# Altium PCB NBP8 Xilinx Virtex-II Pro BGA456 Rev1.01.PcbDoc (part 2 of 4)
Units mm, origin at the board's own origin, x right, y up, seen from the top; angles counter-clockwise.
Board outline 69 x 99.5 mm, 8 copper layers (Top Layer, InternalPlane1, InternalPlane2, MidLayer1, MidLayer2, MidLayer3, MidLayer4, Bottom Layer), stack 1.545 mm thick; 164 components, 314 nets, 1132 pads, 807 vias.
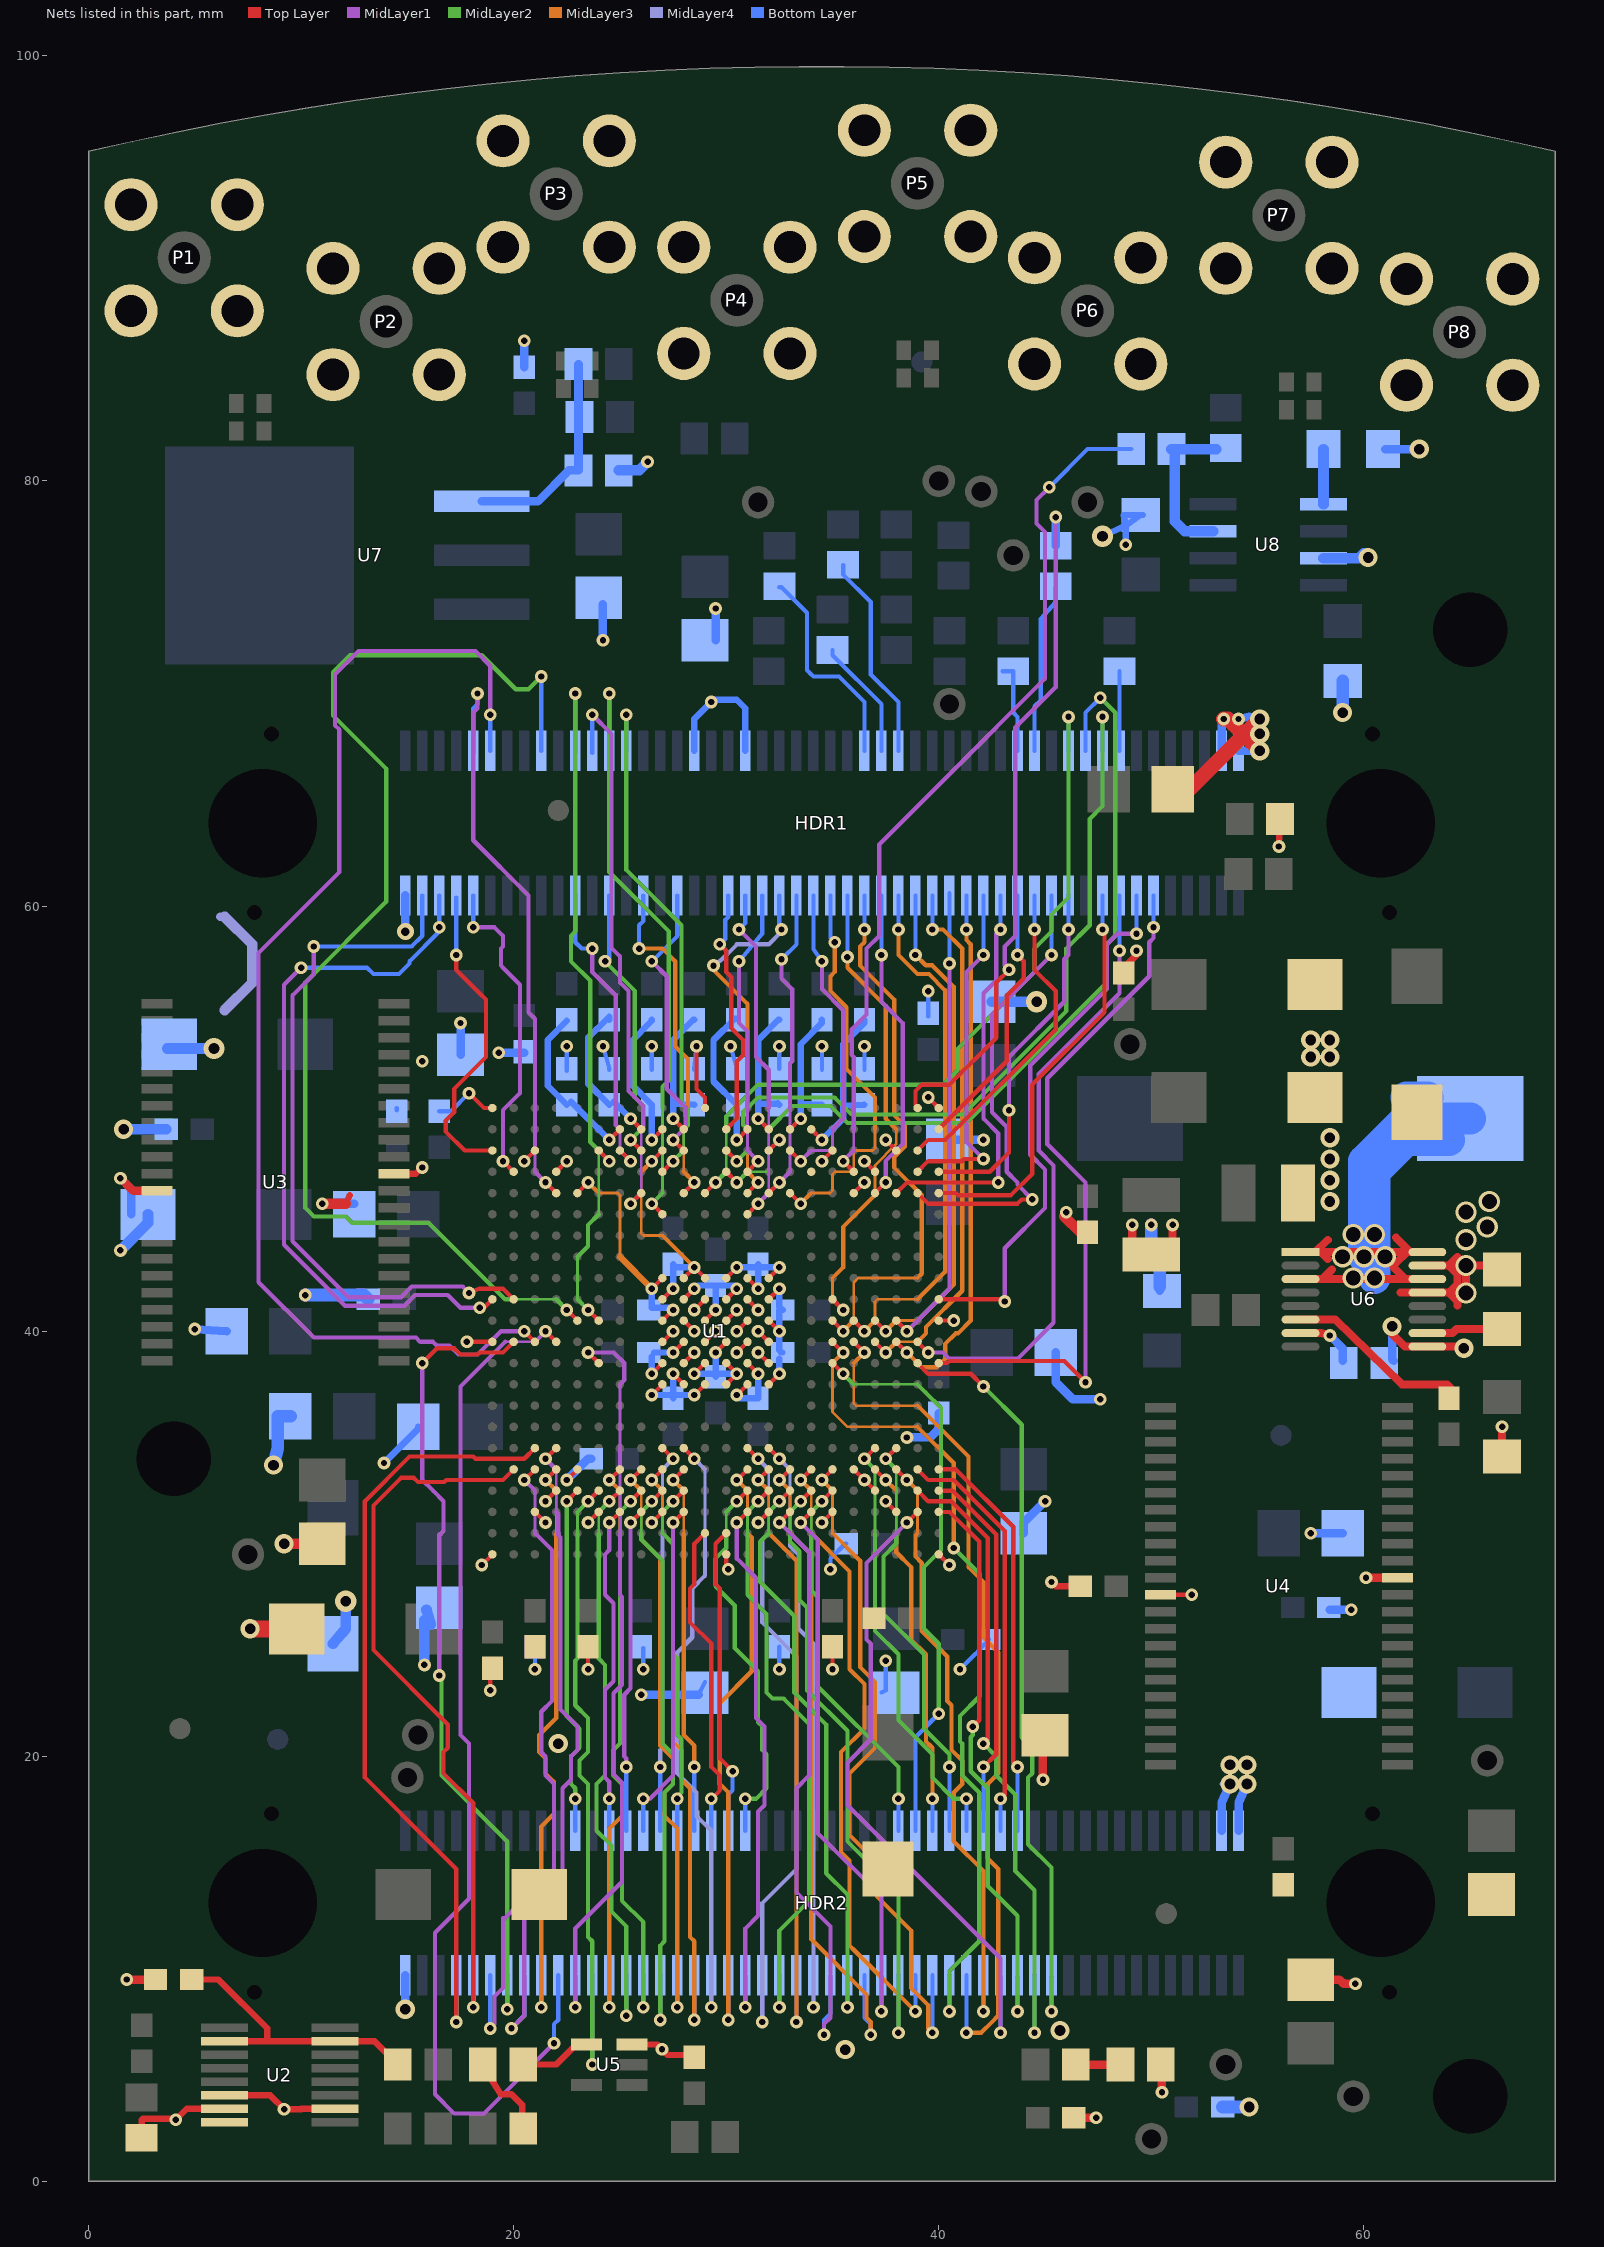
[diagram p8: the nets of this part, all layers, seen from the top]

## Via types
v1: diameter 0.6, hole 0.3, Top Layer to Bottom Layer, tented bottom, 695 vias
v2: diameter 0.9, hole 0.5, Top Layer to Bottom Layer, tented bottom, 45 vias
v3: diameter 1.8, hole 1, Top Layer to Bottom Layer, tented bottom, 26 vias
v4: diameter 1, hole 0.7, Top Layer to Bottom Layer, tented bottom, 17 vias
v5: diameter 1, hole 0.5, Top Layer to Bottom Layer, tented bottom, 15 vias
v6: diameter 1.5, hole 1, Top Layer to Bottom Layer, tented bottom, 4 vias
v7: diameter 0.8, hole 0.4, Top Layer to Bottom Layer, tented bottom, 3 vias
v8: diameter 0.9, hole 0.5, Top Layer to Bottom Layer, 2 vias

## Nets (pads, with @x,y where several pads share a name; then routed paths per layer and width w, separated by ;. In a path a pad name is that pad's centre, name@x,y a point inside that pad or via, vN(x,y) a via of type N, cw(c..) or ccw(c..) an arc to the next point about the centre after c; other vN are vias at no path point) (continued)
GND: C1.2 C2.2 C3.2 C4.2 C5.2 C6.2 C7.2 C9.2 C10.2 C11.2 C12.2 C13.2 C14.2 C15.2 C16.2 C17.2 C18.2 C19.2 C20.2 C21.2 C22.2 C23.2 C24.2 C25.2 C26.2 C27.2 C28.2 C29.2 C30.2 C31.2 C32.1 C33.2 C34.2 C35.2 C36.2 C37.2 C38.2 C39.2 C40.2 C41.2 C42.2 C43.2 C44.2 C45.2 C46.2 C47.2 C48.2 C49.2 C50.2 C51.2 C52.2 C53.2 C54.2 C55.2 C56.2 C57.2 C58.2 C59.2 C60.2 C61.2 C62.1 C63.1 C65.1 C66.1 C67.2 C76.2 C77.2 C78.2 C79.2 C80.1 C81.1 C82.1 C83.1 C84.1 C85.1 C86.1 C87.1 C88.2 C89.2 C90.2 C91.2 C92.1 C93.1 C94.2 HDR1.1 HDR1.36 HDR1.42 HDR1.98 HDR1.100 HDR2.1 HDR2.98 HDR2.100 LED1.2 P1.2 P2.2 P3.2 P4.2 P5.2 P6.2 P7.2 P8.2 R16.2 R18.1 R22.1 R25.2 U1.A1 U1.A11 U1.A22 U1.AB1 U1.AB12 U1.AB22 U1.C3 U1.C6 U1.C9 U1.C14 U1.C17 U1.C20 U1.D4 U1.D19 U1.E5 U1.E18 U1.J9 U1.J10 U1.J11 U1.J12 U1.J13 U1.J14 U1.K9 U1.K10 U1.K11 U1.K12 U1.K13 U1.K14 U1.L9 U1.L10 U1.L11 U1.L12 U1.L13 U1.L14 U1.L22 U1.M1 U1.M9 U1.M10 U1.M11 U1.M12 U1.M13 U1.M14 U1.N9 U1.N10 U1.N11 U1.N12 U1.N13 U1.N14 U1.P9 U1.P10 U1.P11 U1.P12 U1.P13 U1.P14 U1.V5 U1.V18 U1.W4 U1.W19 U1.Y3 U1.Y6 U1.Y9 U1.Y14 U1.Y17 U1.Y20 U2.6 U2.7 U2.8 U2.10 U3.12 U3.34 U4.12 U4.34 U5.3 U6.9 U6.13 U6.15 U8.3 | length 275.5
  Top Layer w0.2: v1(17.8,39.5) 18.8,39.5 U1.L22@19,39.5 ; v1(17.9,51.2) 18.6,50.5 U1.AB22@19,50.5 ; v1(18.5,29) U1.A22@19,29.5 ; v1(18.9,23.1) 18.9,24.15 C33.2@18.9,24.2 ; v1(20.5,48) U1.Y20@21,48.5 ; U1.C20@21,31.5 v1(21.5,31) ; v1(21.5,32) U1.D19@22,32.5 ; U1.W19@22,47.5 v1(22.5,48) ; v1(22.5,33) U1.E18@23,33.5 ; U1.V18@23,46.5 v1(23.5,47) ; v1(23.5,24.1) C78.2@23.5,25.15 ; v1(23.5,31) U1.C17@24,31.5 ; U1.Y17@24,48.5 v1(24.5,48) ; v1(26.5,31) U1.C14@27,31.5 ; v1(26.5,37) U1.J14@27,37.5 ; v1(26.5,38) U1.K14@27,38.5 ; v1(26.5,42) U1.P14@27,42.5 ; v1(26.5,48) U1.Y14@27,48.5 ; U1.L14@27,39.5 v1(27.5,40) ; U1.M14@27,40.5 v1(27.5,41) ; U1.N14@27,41.5 v1(27.5,42) ; v1(27.5,38) U1.J13@28,37.5 ; v1(27.5,39) U1.L13@28,39.5 ; U1.K13@28,38.5 v1(28.5,39) ; U1.M13@28,40.5 v1(28.5,40) ; U1.N13@28,41.5 v1(28.5,42) ; U1.P13@28,42.5 v1(28.5,43) U1.P12@29,42.5 ; v1(28.5,37) U1.J12@29,37.5 ; v1(28.5,38) U1.K12@29,38.5 ; v1(28.5,41) U1.N12@29,41.5 ; v1(28.6,53.4) 28.6,51.4 29,51 U1.AB12@29,50.5 ; U1.L12@29,39.5 v1(29.5,40) ; U1.M12@29,40.5 v1(29.5,41) ; v1(29.5,39) U1.L11@30,39.5 ; U1.A11@30,29.5 30,29.1 v1(30.1,28.8) ; U1.J11@30,37.5 v1(30.5,38) U1.K11@30,38.5 ; U1.M11@30,40.5 v1(30.5,41) ; U1.N11@30,41.5 v1(30.5,42) ; U1.P11@30,42.5 v1(30.5,43) ; v1(30.5,37) U1.J10@31,37.5 ; v1(30.5,39) U1.L10@31,39.5 ; v1(30.5,40) U1.M10@31,40.5 ; U1.K10@31,38.5 v1(31.5,38) ; U1.N10@31,41.5 v1(31.5,41) ; U1.P10@31,42.5 v1(31.5,42) ; v1(31.5,31) U1.C9@32,31.5 ; v1(31.5,39) U1.K9@32,38.5 ; v1(31.5,40) U1.L9@32,39.5 ; U1.J9@32,37.5 v1(32.5,38) ; U1.M9@32,40.5 v1(32.5,40) ; U1.N9@32,41.5 v1(32.5,42) ; U1.P9@32,42.5 v1(32.5,43) ; U1.Y9@32,48.5 v1(32.5,49) ; v1(34.5,31) U1.C6@35,31.5 ; v1(34.5,48) U1.Y6@35,48.5 ; v1(35,24.1) C79.2@35,25.15 ; U1.E5@36,33.5 v1(36.5,33) U1.D4@37,32.5 ; U1.V5@36,46.5 v1(36.5,47) ; v1(36.5,48) U1.W4@37,47.5 ; v1(37.5,32) U1.C3@38,31.5 ; v1(37.5,49) U1.Y3@38,48.5 ; v1(39.5,51) U1.AB1@40,50.5 ; U1.A1@40,29.5 v1(40.5,29) ; U1.M1@40,40.5 v1(40.7,40.5) ; C44.2@44.9,20.9 C44.2@45,21 ; U4.12@50.5,27.6 v1(51.9,27.6)
  Top Layer w0.3: R18.1@2.5,2.05 2.5,2.9 2.55,2.95 4.05,2.95 v1(4.1,2.9) 4.613,3.413 U2.7@6.4,3.413 ; U2.6@6.4,4.048 8.553,4.048 v1(9.2,3.4) 10,3.4 10.012,3.413 U2.10@11.6,3.413 ; 12.1,46 12.287,46.4 ; U3.34@14.375,47.4 15.4,47.4 v1(15.7,47.7) ; U5.3@25.57,6.441 26.759,6.441 v1(26.978,6.222) 27.25,5.95 C35.2@28.5,5.95 ; v1(45.3,28.2) 45.5,28 C27.2@46.65,28 ; C22.2@48.7,56.85 48.5,56.9 48.575,56.975 49.3,57.7 v1(49.3,57.9) ; v1(56,62.8) R16.2@56.05,64.1
  Top Layer w0.38: C62.1@49.1,43.8 v1(49.1,45) ; C62.1@51,43.9 v1(51,45) ; v2@61.3,40.2 61.3,39.9 61.922,39.278 U6.9@62.984,39.278 v2@64.622,39.278 ; 61.717,41.818 U6.13@62.984,41.818 64,41.818 ; U6.15@62.984,43.088 63.988,43.088 ; 64.4,41.2 64.4,41.417 ; C67.2@66.487,43.088 v4(64.8,43.088) ; C65.1@66.5,34.1 v1(66.5,35.5) ; 63.988,43.088 64.394,42.681 64.4,42.675 ; 63.988,43.088 64.394,43.494 64.4,43.5 v4@64.4,43.088 ; 63.988,43.088 v4@64.4,43.088 ; 64,41.818 64.4,41.417 ; 64,41.818 64.018,41.818 ; 64.018,41.818 v4@64.4,41.818 ; 64.018,41.818 64.4,42.2 ; 64.4,41.417 64.4,41.8 v4@64.4,41.818 ; v4@64.4,41.818 64.4,42.2 ; v4@64.4,41.818 64.518,41.818 64.65,41.95 64.8,42.1 v4(64.8,43.088) ; 64.4,42.2 64.4,42.675 ; 64.4,42.675 v4@64.4,43.088 ; v4@64.4,43.088 v4(64.8,43.088)
  Top Layer w0.4: v1(1.5,47.2) 2.1,46.6 U3.12@3.225,46.6 ; v1(1.8,9.5) C32.1@3.15,9.5 ; v1(44.9,18.9) C44.2@44.9,20.9 ; C13.2@46.4,3 v1(47.4,3) ; v1(50.5,4.2) LED1.2@50.5,5.5 ; C60.2@57.5,9.5 58.85,9.5 59.05,9.3 v1(59.6,9.3) ; v1(60.1,28.4) U4.34@61.575,28.4
  Top Layer w0.5: v2(9.2,30) C46.2@11,30 ; v1(11,46) 12.1,46 ; v1(46,45.6) 45.9,45.4 46.65,44.65 C25.2@47,44.65
  Top Layer w0.7: C90.2@51.5,65.4 51.7,65.4 54.35,68.05 ; v1(53.4,68.8) 53.6,68.8 53.85,68.55 54.35,68.05 ; v2(55.1,67.3) 54.7,67.7 54.35,68.05 ; v2(55.1,68.8) 54.75,68.45 54.35,68.05
  Top Layer w0.8: v2(7.6,26) C51.2@9.8,26
  MidLayer3 w0.127: 24,46.5 24.9,46.5 25,46.4 25,43.5 ; 26,47.5 26,44.6 26.1,44.5 27,44.5
  MidLayer3 w0.2: v1(23.5,47) 24,46.5 ; 26,47.5 v1(26.5,48) ; 27,44.5 v1(28.5,43)
  MidLayer3 w0.3: 25,43.5 v1(26.5,42)
  MidLayer4 w0.4: 6.2,59.5 6.4,59.5
  MidLayer4 w0.5: 6.4,55.1 7.7,56.4 7.7,58.2 6.4,59.5
  Bottom Layer w0.2: C34.2@14.5,50.4 C34.2@14.5,50.5 ; C4.2@16.5,50.35 17.05,50.35 v1(17.9,51.2) ; v1(21,24.1) C1.2@21,25.15 ; C81.1@22.5,52.25 C81.1@22.5,52.35 v1(22.5,53.4) ; v1(24.2,53.4) C80.1@24.5,52.35 C80.1@24.5,52.3 ; v1(26.1,24.1) C3.2@26.1,25.1 ; C82.1@26.5,52.3 C82.1@26.5,52.35 v1(26.5,53.4) ; C83.1@28.5,52.3 C83.1@28.5,52.35 v1(28.6,53.4) ; C37.2@28.7,22.9 28.8,23.1 C37.2@29,23.5 ; v1(30.2,53.4) C86.1@30.5,52.35 C86.1@30.5,52.3 ; v1(32.5,24.1) C6.2@32.5,25.15 ; C87.1@32.5,52.35 v1(32.5,53.4) ; C85.1@34.5,52.3 C85.1@34.5,52.35 v1(34.5,53.4) ; v1(34.9,28.8) 34.9,29.3 35.6,30 C23.2@35.65,30 ; C84.1@36.5,52.3 C84.1@36.5,52.35 v1(36.5,53.4) ; C48.2@37.3,23 37.5,23.1 v1(37.5,24.5) ; C5.2@39.5,54.8 C5.2@39.5,54.95 v1(39.5,56) ; v1(41,24.1) 41.7,24.8 C2.2@42.35,25.5 ; v2@53.3,18.7 v2(53.7,18.7) ; HDR2.100@54.1,16.4 HDR2.100@54.1,16.5
  Bottom Layer w0.3: v1(13.9,33.8) 15.5,35.4 C50.2@15.5,35.5 ; v1(26.5,37) C21.2@27.5,37 ; v1(26.5,38) C14.2@26.5,38.8 ; v1(26.5,42) 26.5,41.1 27.4,41.1 v1(27.5,41) ; C14.2@26.6,39 v1(27.5,39) ; C21.2@27.5,36.85 C21.2@27.5,37 ; v1(27.5,38) C21.2@27.5,37 ; v1(27.5,42) C19.2@27.5,43.15 ; C19.2@27.6,43 v1(28.5,43) ; v1(28.5,37) C21.2@27.5,37 ; v1(28.5,38) C12.2@29.4,38 ; v1(28.5,42) 28.65,42.15 C10.2@29.5,42.15 ; HDR1.36@28.5,67.3 28.5,68.8 v1(29.3,69.6) 29.4,69.7 30.5,69.7 30.9,69.3 HDR1.42@30.9,67.3 ; C12.2@29.5,37.85 C12.2@29.5,38 ; v1(29.5,39) C12.2@29.5,38 ; v1(29.5,41) C10.2@29.5,42.15 ; v1(30.5,37) 30.65,36.85 C20.2@31.5,36.85 v1(31.5,38) ; v1(30.5,38) C12.2@29.5,38 ; v1(30.5,42) 30.35,42.15 C10.2@29.5,42.15 ; v1(30.5,43) C18.2@31.5,43 ; v1(31.5,42) C18.2@31.5,43 ; C18.2@31.5,43.15 C18.2@31.5,43 ; v1(32.5,38) C9.2@32.5,38.7 ; C16.2@32.5,41 v1(32.5,40) 32.5,39.1 32.6,39 C9.2@32.65,39 ; v1(32.5,42) 32.5,41.15 C16.2@32.65,41 ; v1(32.5,43) C18.2@31.5,43 ; v5(47.7,77.4) C92.1@48.8,77.9 ; v1(48.8,77) C92.1@48.8,77.9 ; C92.1@49.6,78.4 C92.1@49.5,78.4 ; C92.1@48.8,77.9 48.731,78.246 48.7,78.4 C92.1@49.5,78.4 ; C92.1@48.8,77.9 C92.1@49.5,78.4
  Bottom Layer w0.4: v1(1.5,47.2) 2,46.7 C56.2@2,45.5 ; v1(5,40.1) C47.2@6.5,40 ; v1(10.2,41.7) 11.6,41.7 ; v1(11,46) C41.2@12.5,46 ; v2@14.9,8.2 HDR2.1@14.9,9.7 ; v7(14.9,58.8) HDR1.1@14.9,60.5 ; C89.2@17.5,53 v1(17.5,54.5) ; v1(19.3,53.1) C77.2@20.5,53.1 ; C17.2@20.5,85.35 v1(20.5,86.6) ; v1(22.5,33) 23.5,34 C24.2@23.65,34 ; v1(24.2,72.5) C59.2@24.2,74.2 ; v1(26,22.9) C37.2@28.7,22.9 ; C45.2@29.5,72.5 v1(29.5,74) ; v1(38.5,35) 39.6,35 40,35.4 C7.2@40,36.15 ; C43.2@40.5,49 v1(42.1,49) ; C40.2@44,30.5 44,31 v1(45,32) ; C39.2@45.5,39 45.5,37.6 46.3,36.8 v1(47.6,36.8) ; 50,43.9 50.4,43.5 C66.1@50.4,41.9 ; HDR2.98@53.3,16.5 53.3,17.8 v2(53.7,18.7) ; HDR1.98@53.3,67.3 53.3,68.6 53.45,68.75 53.6,68.9 v1(54.1,68.8) ; HDR2.100@54.1,16.5 54.1,17.8 v2(54.5,18.7) ; v2(55.1,67.3) HDR1.100@54.1,67.3 v1(54.1,68.8) ; v2(55.1,68.1) 54.785,68.603 54.74,68.675 54.6,68.9 v1(54.1,68.8) ; v1(57.5,30.5) C49.2@59,30.5 ; C15.2@58.4,26.9 v1(59.4,26.9) ; C94.2@61,81.5 v2(62.6,81.5) ; v2(61.329,40.229) 61.329,38.671 R22.1@61.4,38.6
  Bottom Layer w0.5: v1(1.5,43.8) 2.8,45.1 C56.2@2.8,45.5 ; v2(1.65,49.5) 3.3,49.5 C26.2@3.65,49.5 ; C91.2@3.7,53.3 3.8,53.3 v5(5.9,53.3) ; C54.2@11.5,25.3 12.1,26 v5(12.1,27.3) ; v1(15.8,24.3) 15.8,26.4 16.008,26.262 16.1,26.2 15.919,26.834 C42.2@15.9,26.9 ; R25.2@24.95,80.5 25.9,80.5 v1(26.3,80.9) ; C38.2@42.5,55.5 v5(44.6,55.5) ; U8.3@58.1,76.365 59.765,76.365 60,76.6 v2(60.2,76.4)
  Bottom Layer w0.6: v2(8.7,33.7) 8.9,34.5 8.9,36 C36.2@9.5,36 ; v1(10.2,41.7) 12.95,41.7 C29.2@13.15,41.5 ; v1(50,45) 50,43.9 50.4,43.5 C66.1@50.4,42.1 ; C28.2@53.35,3.5 v2(54.6,3.5) ; v2(59,69.1) C93.1@59,70.6
  other v1: 15.7,52.7
  other v2: 35.6,6.2 45.7,7.1 14.9,8.1 53.7,19.6 54.5,19.6 22.1,20.6 64.7,39.2 58.4,46.1 58.4,47.1 58.4,48.1 58.4,49.1 57.5,52.9 58.4,52.9 57.5,53.7 58.4,53.7
  other v4: 64.8,41.8 64.8,44.3 65.8,44.9 64.8,45.6 65.9,46.1
GREEN0: HDR1.10 U1.V19 | length 28.1
  Top Layer w0.2: v1(21.5,47) U1.V19@22,46.5
  MidLayer1 w0.127: 21,47.5 21,48.5
  MidLayer1 w0.2: v1(18.3,70) 18.3,69.3 18.1,69.1 18.1,63.1 20.7,60.5 20.7,55 21,54.7 21,48.5 ; 21,47.5 v1(21.5,47)
  Bottom Layer w0.2: HDR1.10@18.1,67.2 HDR1.10@18.1,67.3 18.1,69.3 18.3,69.5 v1(18.3,70)
GREEN1: HDR1.12 U1.L20 | length 57.4
  Top Layer w0.2: v1(20.5,40) U1.L20@21,39.5
  MidLayer1 w0.2: v1(18.9,69) 18.9,71.3 18.2,72 12.7,72 11.6,70.9 11.6,68.5 11.8,68.3 11.8,61.6 8,57.8 8,42.3 10.6,39.7 15.4,39.7 15.6,39.5 16.2,39.5 16.386,39.314 16.986,39.314 17.4,38.9 18.3,38.9 19.4,40 v1(20.5,40)
  Bottom Layer w0.2: HDR1.12@18.9,67.3 v1(18.9,69)
HDRIVE: HDR1.18 U1.M18 | length 57.3
  Top Layer w0.2: v1(22.5,41) U1.M18@23,40.5
  MidLayer2 w0.127: 20,41.5 22,41.5
  MidLayer2 w0.2: 20,41.5 19.6,41.5 16,45.1 12.4,45.1 12.1,45.4 10.6,45.4 10.2,45.8 10.2,56.4 14,60.2 14,66.466 11.5,68.966 11.5,71 12.1,71.6 12.3,71.8 18.5,71.8 20.1,70.2 20.7,70.2 v1(21.3,70.8) ; 22,41.5 v1(22.5,41)
  Bottom Layer w0.2: HDR1.18@21.3,67.3 21.3,70 v1(21.3,70.8)
IO0: HDR2.7 U1.F20 | length 37.6
  Top Layer w0.2: v1(17.3,7.5) 17.3,14.7 16.379,15.621 13,19 13,32 15.1,34.1 18.1,34.1 18.2,34 20.5,34 U1.F20@21,34.5
  Bottom Layer w0.2: v1(17.3,7.5) HDR2.7@17.3,9.7
IO1: HDR2.9 U1.E21 | length 34.7
  Top Layer w0.2: v1(18.1,8.2) 18.1,17.8 16.7,19.2 16.7,20.2 16.9,20.4 16.9,21.5 13.4,25 13.4,31.8 14.7,33.1 15.3,33.1 15.5,32.9 16.732,32.9 16.832,33 19.5,33 U1.E21@20,33.5
  Bottom Layer w0.2: v1(18.1,8.2) HDR2.9@18.1,9.7
IO2: HDR2.11 U1.E20 | length 31.3
  Top Layer w0.2: v1(20.5,33) U1.E20@21,33.5
  MidLayer1 w0.127: 21,30.5 21,32.5
  MidLayer1 w0.2: v1(18.9,7.2) 19.1,7.4 19.1,8.7 19.5,9.1 19.5,12.4 ; 19.5,12.3 21.9,14.7 21.9,18.7 21.5,19.1 21.5,20 21.3,20.2 21.3,22.1 21.8,22.6 21.8,29.7 21,30.5 ; v1(20.5,33) 21,32.5
  Bottom Layer w0.2: v1(18.9,7.2) HDR2.11@18.9,9.7
IO3: HDR2.13 U1.L21 | length 38.8
  Top Layer w0.2: v1(15.7,38.5) 16.4,39.2 17.2,39.2 17.5,38.9 18.3,38.9 18.4,39 19.5,39 U1.L21@20,39.5
  MidLayer1 w0.2: v1(15.7,38.5) 15.7,33 16.2,32.5 16.7,32 16.7,30.6 16.5,30.4 v1(16.5,23.8)
  MidLayer2 w0.2: v1(16.5,23.8) 16.6,23.7 16.6,19.1 19.7,16 v1(19.7,8.1)
  Bottom Layer w0.2: v1(19.7,8.1) HDR2.13@19.7,9.7
IO4: HDR2.15 U1.F19 | length 32.2
  Top Layer w0.2: v1(21.5,34) U1.F19@22,34.5
  MidLayer1 w0.127: 22,31.5 22,33.5
  MidLayer1 w0.2: v1(19.9,7.2) 20.5,7.8 20.5,12.4 22.3,14.2 22.3,18.5 22.7,18.9 22.7,20 23,20.3 23,21.4 22.2,22.2 22.2,30.3 22.1,30.4 22.1,31.4 22,31.5 ; v1(21.5,34) 22,33.5
  Bottom Layer w0.2: v1(19.9,7.2) 20.5,7.8 HDR2.15@20.5,9.7
IO5: HDR2.17 U1.E19 | length 28.1
  Top Layer w0.2: v1(21.5,33) U1.E19@22,33.5
  MidLayer3 w0.127: 22,30.5 22,32.5
  MidLayer3 w0.2: v1(21.3,8.2) 21.3,16.7 21.9,17.3 21.9,18.8 21.5,19.2 21.5,19.9 21.2,20.2 21.2,21 22,21.8 22,30.5 ; v1(21.5,33) 22,32.5
  Bottom Layer w0.2: v1(21.3,8.2) HDR2.17@21.3,9.7
IO6: HDR2.19 U1.L19 | length 50.5
  Top Layer w0.2: v1(21.5,40) U1.L19@22,39.5
  MidLayer1 w0.127: 19.6,39.5 21,39.5
  MidLayer1 w0.2: 19.6,39.5 17.5,37.4 17.5,21 17.9,20.6 17.9,13.3 16.3,11.7 16.3,4.1 17.2,3.2 18.6,3.2 v1(21.9,6.5) ; 21,39.5 v1(21.5,40)
  Bottom Layer w0.2: v1(21.9,6.5) 21.9,7.4 22.1,7.6 HDR2.19@22.1,9.7
IO7: HDR2.21 U1.K17 | length 35.8
  Top Layer w0.2: v1(23.5,39) U1.K17@24,38.5
  MidLayer1 w0.127: 25,30.5 25,33.5 ; 25,34.5 25,37.5
  MidLayer1 w0.2: v1(22.9,8.2) 22.9,11.9 25.1,14.1 25.1,18.766 24.7,19.166 24.7,22.966 25.1,23.366 25.1,27.5 25,27.6 25,30.5 ; v1(23.5,39) 24.7,39 25.2,38.5 25.2,37.7 25,37.5 ; 25,33.5 25,34.5
  Bottom Layer w0.2: v1(22.9,8.2) HDR2.21@22.9,9.7
IO8: HDR2.23 U1.D17 | length 32.3
  Top Layer w0.2: v1(23.5,32) U1.D17@24,32.5
  MidLayer2 w0.127: 23,30.5 23,31.5
  MidLayer2 w0.2: 23,30.5 23,24.6 22.9,24.5 22.9,22.4 23.5,21.8 23.5,20.2 23.1,19.8 23.1,19.1 23.5,18.7 23.5,11.5 23.7,11.3 v1(23.7,5.5) ; 23,31.5 v1(23.5,32)
  Bottom Layer w0.2: v1(23.7,5.5) HDR2.23@23.7,9.7
IO9: HDR2.25 U1.E16 | length 27.8
  Top Layer w0.2: v1(24.5,33) U1.E16@25,33.5
  MidLayer3 w0.127: 25,30.5 25,32.5
  MidLayer3 w0.2: v1(24.5,8.2) 24.5,16.6 25.1,17.2 25.1,18.7 24.7,19.1 24.7,20.3 25,20.6 25,30.5 ; v1(24.5,33) 25,32.5
  Bottom Layer w0.2: v1(24.5,8.2) HDR2.25@24.5,9.7
IO10: HDR2.27 U1.D16 | length 27.9
  Top Layer w0.2: v1(24.5,32) U1.D16@25,32.5
  MidLayer2 w0.127: 24,30.5 24,31.5
  MidLayer2 w0.2: 24,30.5 24,24.6 24.3,24.3 24.3,19.1 23.9,18.7 23.9,16.5 24.6,15.8 24.6,12.7 25.3,12 v1(25.3,7.8) ; 24,31.5 v1(24.5,32)
  Bottom Layer w0.2: v1(25.3,7.8) 25.3,8.2 HDR2.27@25.3,9.7
IO11: HDR2.29 U1.D15 | length 26.9
  Top Layer w0.2: v1(25.5,32) U1.D15@26,32.5
  MidLayer2 w0.127: 25,30.5 25,31.5
  MidLayer2 w0.2: 25,30.5 25,20.6 24.7,20.3 24.7,19.1 25.1,18.7 25.1,13.2 26.1,12.2 v1(26.1,8.2) ; 25,31.5 v1(25.5,32)
  Bottom Layer w0.2: v1(26.1,8.2) HDR2.29@26.1,9.7
IO12: HDR2.31 U1.D14 | length 28.3
  Top Layer w0.2: v1(26.5,32) U1.D14@27,32.5
  MidLayer2 w0.127: 26,30.5 26,31.5
  MidLayer2 w0.2: 26,30.5 26,30.2 27,29.2 27,20.6 27.5,20.1 27.5,18.7 27.1,18.3 27.1,11.3 26.9,11.1 v1(26.9,7.6) ; 26,31.5 v1(26.5,32)
  Bottom Layer w0.2: v1(26.9,7.6) HDR2.31@26.9,9.7
IO13: HDR2.33 U1.E15 | length 28.2
  Top Layer w0.2: v1(25.5,33) U1.E15@26,33.5
  MidLayer3 w0.127: 26,30.5 26,32.5
  MidLayer3 w0.2: v1(25.5,33) 26,32.5 ; 26,30.5 26,30.2 26.9,29.3 26.9,20.5 27.5,19.9 27.5,18.7 27.1,18.3 27.1,17.2 27.7,16.6 v1(27.7,8.2)
  Bottom Layer w0.2: v1(27.7,8.2) HDR2.33@27.7,9.7
IO14: HDR2.35 U1.E14 | length 29
  Top Layer w0.2: v1(26.5,33) U1.E14@27,33.5
  MidLayer3 w0.127: 27,30.5 27,32.5
  MidLayer3 w0.2: v1(26.5,33) 27,32.5 ; 27,30.5 27.5,30 27.5,20.7 27.9,20.3 27.9,18.9 28.3,18.5 28.3,11.5 28.5,11.3 v1(28.5,7.6)
  Bottom Layer w0.2: v1(28.5,7.6) HDR2.35@28.5,9.7
IO15: HDR2.37 U1.F13 | length 29.4
  Top Layer w0.2: U1.F13@28,34.5 v1(28.5,34)
  MidLayer4 w0.127: 29,30.5 29,33.5
  MidLayer4 w0.2: v1(28.5,34) 29,33.5 ; 29,30.5 29,28.5 28.4,27.9 28.4,25.6 27.7,24.9 27.7,19.2 28.6,18.3 28.6,17.2 29.3,16.5 v1(29.3,8.2)
  Bottom Layer w0.2: v1(29.3,8.2) HDR2.37@29.3,9.7
IO16: HDR2.39 U1.E10 | length 29.3
  Top Layer w0.2: v1(30.5,33) U1.E10@31,33.5
  MidLayer3 w0.127: 31,30.5 31,32.5
  MidLayer3 w0.2: v1(30.1,7.6) 30.1,18.3 29.7,18.7 29.7,22.5 31.2,24 31.2,30.3 31,30.5 ; v1(30.5,33) 31,32.5
  Bottom Layer w0.2: v1(30.1,7.6) HDR2.39@30.1,9.7
IO17: HDR2.41 U1.C10 | length 25.9
  Top Layer w0.2: v1(30.5,31) U1.C10@31,31.5
  MidLayer1 w0.2: v1(30.5,31) 30.5,29.3 31.4,28.4 31.4,21.8 31.8,21.4 31.8,17.7 31.5,17.4 31.5,12.5 30.9,11.9 v1(30.9,8.2)
  Bottom Layer w0.2: v1(30.9,8.2) HDR2.41@30.9,9.7
IO18: HDR2.43 U1.F10 | length 31.1
  Top Layer w0.2: U1.F10@31,34.5 v1(31.5,34)
  MidLayer4 w0.127: 32,30.5 32,33.5
  MidLayer4 w0.2: v1(31.5,34) 32,33.5 ; v1(31.7,7.5) 31.7,13.1 33.3,14.7 33.3,24.7 31.7,26.3 31.7,30.2 32,30.5
  Bottom Layer w0.2: v1(31.7,7.5) HDR2.43@31.7,9.7
IO19: HDR2.45 U1.D9 | length 28.3
  Top Layer w0.2: v1(31.5,32) U1.D9@32,32.5
  MidLayer2 w0.127: 31,30.5 31,31.5
  MidLayer2 w0.2: 31,30.5 31,27.6 31.9,26.7 31.9,23 32.179,22.721 32.7,22.721 33.9,21.521 33.9,13.2 33.379,12.679 32.5,11.8 v1(32.5,8.2) ; 31,31.5 v1(31.5,32)
  Bottom Layer w0.2: v1(32.5,8.2) HDR2.45@32.5,9.7
IO20: HDR2.47 U1.E9 | length 29.1
  Top Layer w0.2: v1(31.5,33) U1.E9@32,33.5
  MidLayer3 w0.127: 32,30.5 32,32.5
  MidLayer3 w0.2: v1(31.5,33) 32,32.5 ; 32,30.5 32.707,29.793 33.3,29.2 v1(33.3,7.5)
  Bottom Layer w0.2: v1(33.3,7.5) HDR2.47@33.3,9.6
IO21: HDR2.49 U1.F9 | length 28.7
  Top Layer w0.2: U1.F9@32,34.5 v1(32.5,34)
  MidLayer4 w0.127: 33,30.5 33,33.5
  MidLayer4 w0.2: v1(32.5,34) 33,33.5 ; 33,30.5 33,29.9 33.4,29.5 33.4,26 34.1,25.3 v1(34.1,8.2)
  Bottom Layer w0.2: v1(34.1,8.2) HDR2.49@34.1,9.7
IO22: HDR2.51 U1.C8 | length 29.3
  Top Layer w0.2: v1(32.5,31) U1.C8@33,31.5
  MidLayer1 w0.2: v1(32.5,31) 33.9,29.6 33.9,19.1 33.3,18.5 33.3,13.6 34.9,12 34.9,7.7 34.6,7.4 v1(34.6,6.9)
  Bottom Layer w0.2: v1(34.6,6.9) 34.6,7.6 34.9,7.9 HDR2.51@34.9,9.7
IO23: HDR2.53 U1.D8 | length 28.3
  Top Layer w0.2: v1(32.5,32) U1.D8@33,32.5
  MidLayer2 w0.127: 32,30.5 32,31.5
  MidLayer2 w0.2: 32,27.8 32.047,27.753 ; 32,30.5 31.6,30.1 31.6,28.2 32.047,27.753 ; 32,31.5 v1(32.5,32) ; v1(35.7,8.2) 35.7,13.5 34.7,14.5 34.7,21.5 33.2,23 33.2,26.6 32.047,27.753
  Bottom Layer w0.2: v1@35.7,8 v1(35.7,8.2) HDR2.53@35.7,9.7
IO24: HDR2.55 U1.E8 | length 31.5
  Top Layer w0.2: v1(32.5,33) U1.E8@33,33.5
  MidLayer3 w0.127: 33,30.5 33,32.5
  MidLayer3 w0.2: v1(32.5,33) 33,32.5 ; 33,30.5 34,29.5 34,11.4 36.6,8.8 36.6,7.7 36.8,7.5 v1(36.8,6.9)
  Bottom Layer w0.2: HDR2.55@36.5,9.7 36.5,7.7 36.8,7.4 v1(36.8,6.9)
IO25: HDR2.57 U1.C7 | length 27
  Top Layer w0.2: v1(33.5,31) U1.C7@34,31.5
  MidLayer1 w0.2: v1(33.5,31) 34.3,30.2 34.3,16.4 37.3,13.4 v1(37.3,8)
  Bottom Layer w0.2: v1(37.3,8) HDR2.57@37.3,9.7
IO26: HDR2.59 U1.D7 | length 30.7
  Top Layer w0.2: v1(33.5,32) U1.D7@34,32.5
  MidLayer2 w0.127: 33,30.5 33,31.5
  MidLayer2 w0.2: 33,30.5 33,30.1 33.449,29.651 33.449,27.351 33.8,27 33.8,23.1 35.7,21.2 35.7,16 38.1,13.6 v1(38.1,7) ; 33,31.5 v1(33.5,32)
  Bottom Layer w0.2: v1(38.1,7) HDR2.59@38.1,9.7
IO27: HDR2.61 U1.E7 | length 30.6
  Top Layer w0.2: v1(33.5,33) U1.E7@34,33.5
  MidLayer3 w0.127: 34,30.5 34,32.5
  MidLayer3 w0.2: v1(33.5,33) 34,32.5 ; 34,30.5 35.8,28.7 35.8,24.1 36.5,23.4 36.5,21.3 35.4,20.2 35.4,15.5 35.8,15.1 35.8,11.1 36.048,10.852 v1(38.9,8)
  Bottom Layer w0.2: v1(38.9,8) HDR2.61@38.9,9.7
IO28: HDR2.63 U1.E6 | length 32.6
  Top Layer w0.2: v1(34.5,33) U1.E6@35,33.5
  MidLayer3 w0.127: 35,30.5 35,32.5
  MidLayer3 w0.2: v1(34.5,33) 35,32.5 ; 35,30.5 36.3,29.2 36.3,24.2 37,23.5 37,20.4 35.8,19.2 35.8,16.3 37.1,15 37.1,13.4 38.7,11.8 38.7,9.1 39.5,8.3 39.5,7.2 v1(39.7,7)
  Bottom Layer w0.2: v1(39.7,7) HDR2.63@39.7,9.7
IO29: HDR2.65 U1.L6 | length 39.8
  Top Layer w0.2: U1.L6@35,39.5 v1(35.5,39)
  MidLayer2 w0.2: v1(40.5,8) 40.5,9.9 41.9,11.3 41.9,18.3 41.1,19.1 41.1,20.6 41,20.7 41,21.9 41.9,22.8 41.9,28.6 v1(40.7,29.8) ; v1@40.6,29.8 v1@40.65,29.75
  MidLayer3 w0.127: 35,38.5 35,36.2 35.7,35.5 39,35.5
  MidLayer3 w0.2: 35,38.5 v1(35.5,39) ; 39,35.5 40.7,33.8 v1(40.7,29.8)
  Bottom Layer w0.2: v1(40.5,8) HDR2.65@40.5,9.7
IO30: HDR2.67 U1.L5 | length 41.7
  Top Layer w0.2: U1.L5@36,39.5 v1(36.5,39)
  MidLayer3 w0.127: 36,38.5 36,36.6 36.1,36.5 39,36.5
  MidLayer3 w0.2: 36,38.5 v1(36.5,39) ; 39,36.5 41.4,34.1 41.4,28.9 42.1,28.2 42.1,25.6 42.8,24.9 42.8,19.2 42.3,18.7 42.3,15.2 42.8,14.7 42.8,7.8 42.5,7.5 42,7 v1(41.3,7) v1@41.2,7
  Bottom Layer w0.2: v1(41.3,7) HDR2.67@41.3,9.7
IO31: HDR2.69 U1.E3 | length 29.2
  Top Layer w0.2: U1.E3@38,33.5 v1(38.5,33)
  MidLayer3 w0.127: 39,30.5 39,32.5
  MidLayer3 w0.2: v1(38.5,33) 39,32.5 ; 39,30.5 38.9,30.4 38.9,29.4 39.2,29.1 39.2,25.9 40.4,24.7 40.4,22.6 40.6,22.4 40.6,20.3 41.1,19.8 41.1,18.7 40.7,18.3 40.7,16 42.1,14.6 v1(42.1,8)
  Bottom Layer w0.2: v1(42.1,8) HDR2.69@42.1,9.6
IO32: HDR2.71 U1.C2 | length 31.7
  Top Layer w0.2: v1(38.5,31) U1.C2@39,31.5
  MidLayer1 w0.2: v1(38.5,31) 36.6,29.1 36.6,25.5 36.8,25.3 36.8,20.8 35.7,19.7 35.7,17.7 42.9,10.5 v1(42.9,7)
  Bottom Layer w0.2: v1(42.9,7) HDR2.71@42.9,9.7
IO33: HDR2.73 U1.C1 | length 27.3
  Top Layer w0.2: U1.C1@40,31.5 40.503,31.5 41.9,30.103 41.9,21.7 v1(41.6,21.4)
  MidLayer2 w0.2: v1(41.6,21.4) 41.6,21 41.5,20.9 41.5,19.3 42.3,18.5 42.3,13.9 43.7,12.5 v1(43.7,8)
  Bottom Layer w0.2: v1(43.7,8) HDR2.73@43.7,9.6
IO34: HDR2.75 U1.D2 | length 31.3
  Top Layer w0.2: U1.D2@39,32.5 39.5,32 40.569,32 42.3,30.269 42.3,20.8 v1(42.1,20.6)
  MidLayer2 w0.2: v1(42.1,20.6) 42.7,20 42.7,19.1 43.6,18.2 43.6,14.6 44.5,13.7 v1(44.5,7)
  Bottom Layer w0.2: v1(44.5,7) HDR2.75@44.5,9.7
IO35: HDR2.77 U1.K2 | length 36
  Top Layer w0.2: U1.K2@39,38.5 39.5,38 41.5,38 v1(42.1,37.4)
  MidLayer2 w0.2: v1(42.1,37.4) 43.9,35.6 43.9,20.9 44.4,20.4 44.4,19.2 44.2,19 44.2,15.866 45.3,14.766 v1(45.3,8)
  Bottom Layer w0.2: v1(45.3,8) HDR2.77@45.3,9.6
JIOA0: HDR1.3 U1.N21 | length 33.6
  Top Layer w0.2: v1(17.9,41.8) 18.4,42 19.5,42 U1.N21@20,41.5
  MidLayer1 w0.2: v1(10.6,58.1) 10.6,56.8 9.6,55.8 9.6,44.231 12.231,41.6 14.7,41.6 15.2,42.1 17.6,42.1 v1(17.9,41.8)
  Bottom Layer w0.2: v1(10.6,58.1) 15.2,58.1 15.7,58.6 HDR1.3@15.7,60.5
JIOA1: HDR1.5 U1.N22 | length 34.2
  Top Layer w0.2: v1(18.4,41.1) 18.6,41.1 U1.N22@19,41.5
  MidLayer1 w0.2: v1(10,57.1) 9.2,56.3 9.2,44.066 12.066,41.2 14.866,41.2 15.366,41.7 16.9,41.7 17.5,41.1 v1(18.4,41.1)
  Bottom Layer w0.2: v1(10,57.1) 13.1,57.1 13.4,56.8 14.6,56.8 15.1,57.3 15.1,57.4 16.5,58.8 v1(16.5,59) HDR1.5@16.5,60.5
JIOA2: HDR1.7 U1.Y22 | length 14.9
  Top Layer w0.2: v1(17.3,57.7) 17.3,57 18.4,55.9 18.7,55.6 18.7,52.9 17.2,51.4 17.2,50.3 16.8,49.9 16.8,49.4 17.7,48.5 U1.Y22@19,48.5
  Bottom Layer w0.2: v1(17.3,57.7) HDR1.7@17.3,60.4
JIOA3: HDR1.9 U1.W21 | length 15.1
  Top Layer w0.2: v1(19.5,48) U1.W21@20,47.5
  MidLayer1 w0.2: v1(18.1,59) 19.1,59 19.5,58.6 19.5,58.1 19.4,58 19.4,57.2 19.5,57.1 20.3,56.3 20.3,51.2 19.5,50.4 v1(19.5,48)
  Bottom Layer w0.2: v1(18.1,59) HDR1.9@18.1,60.5
JIOB0: HDR1.83 U1.V1 | length 19.4
  Top Layer w0.2: U1.V1@40,46.5 40.8,46.5 40.9,46.4 43.4,46.4 44.4,47.4 44.4,51.6 47.8,55 v1@47.8,58.9
  Bottom Layer w0.2: v1(47.7,58.9) HDR1.83@47.7,60.5
JIOB1: HDR1.85 U1.L2 | length 29.4
  Top Layer w0.2: U1.L2@39,39.5 v1(39.5,39)
  MidLayer1 w0.2: v1(39.5,39) 40.2,39 40.5,38.7 43.7,38.7 45.4,40.4 45.4,47.8 44.7,48.5 44.7,52.1 48.5,55.9 v1(48.5,57.9)
  Bottom Layer w0.2: v1(48.5,57.9) HDR1.85@48.5,60.5
JIOB2: HDR1.87 U1.N1 | length 25.9
  Top Layer w0.2: U1.N1@40,41.5 42.9,41.5 43,41.4 v1(43.1,41.4)
  MidLayer1 w0.2: v1(43.1,41.4) 43.1,43.9 45,45.8 45,47.6 44.3,48.3 44.3,52.5 47.9,56.1 47.9,58.2 48.4,58.7 v1(49.3,58.7)
  Bottom Layer w0.2: v1(49.3,58.7) HDR1.87@49.3,60.5
JIOB3: HDR1.89 U1.K1 | length 33.4
  Top Layer w0.2: U1.K1@40,38.5 40.4,38.5 40.5,38.6 45.9,38.6 v1(46.9,37.6) v1@47,37.5
  MidLayer1 w0.2: v1(46.9,37.6) 46.9,47 45.1,48.8 45.1,51.9 49.9,56.7 49.9,58.3 50.1,58.5 v1(50.1,59) v1@50.2,58.9
  Bottom Layer w0.2: v1(50.1,59) HDR1.89@50.1,60.5
KBCLOCK: HDR1.22 U1.M17 | length 33.7
  Top Layer w0.2: v1(23.5,41) U1.M17@24,40.5
  MidLayer2 w0.127: 23,41.5 23,43.5 ; 24,45.5 24,48.5
  MidLayer2 w0.2: v1(22.9,70) 22.9,58.8 22.7,58.6 22.7,57.4 23.6,56.5 23.6,48.9 24,48.5 ; 23,41.5 v1(23.5,41) ; 23,43.5 23.5,44 23.5,45 24,45.5
  Bottom Layer w0.2: HDR1.22@22.9,67.2 HDR1.22@22.9,67.3 v1(22.9,70)
KBDATA: HDR1.24 U1.V15 | length 26.7
  Top Layer w0.2: v1(25.5,46) U1.V15@26,46.5
  MidLayer1 w0.127: 26,46.5 26,49.5
  MidLayer1 w0.2: v1(23.7,69) 24.6,68.1 24.6,58.034 25,57.634 25,56.4 25.4,56 25.4,51.3 26.1,50.6 26.1,49.6 26,49.5 ; v1(25.5,46) 26,46.5
  Bottom Layer w0.2: HDR1.24@23.7,67.2 HDR1.24@23.7,67.3 v1(23.7,69)
LCD_BCKL: HDR2.22 U1.D18 | length 16.7
  Top Layer w0.2: v1(22.5,32) U1.D18@23,32.5
  MidLayer2 w0.2: v1(22.5,32) 22.5,21.9 23.1,21.3 23.1,20.4 22.7,20 22.7,18.7 22.9,18.5 v1(22.9,18)
  Bottom Layer w0.2: HDR2.22@22.9,16.5 v1(22.9,18)
LCD_E: HDR2.26 U1.C16 | length 15.7
  Top Layer w0.2: v1(24.5,31) U1.C16@25,31.5
  MidLayer1 w0.2: v1(24.5,18) 24.5,18.8 24.3,19 24.3,23.131 24.7,23.531 24.7,27.2 24.3,27.6 24.3,29.5 24.5,29.7 v1(24.5,31)
  Bottom Layer w0.2: HDR2.26@24.5,16.5 v1(24.5,18)
LED0: HDR2.60 U1.D6 | length 18.1
  Top Layer w0.2: v1(34.5,32) U1.D6@35,32.5
  MidLayer2 w0.127: 34,30.5 34,31.5
  MidLayer2 w0.2: 34,30.5 34,27.8 34.3,27.5 34.3,23.3 38.1,19.5 v1(38.1,18) ; 34,31.5 v1(34.5,32)
  Bottom Layer w0.2: HDR2.60@38.1,16.5 v1(38.1,18)
LED1: HDR2.62 U1.K6 | length 26.9
  Top Layer w0.2: U1.K6@35,38.5 v1(35.5,38)
  MidLayer2 w0.127: 36,37.5 39,37.5
  MidLayer2 w0.2: v1(35.5,38) 36,37.5 ; 39,37.5 39.4,37.1 40.1,36.4 40.1,29.7 39.3,28.9 39.3,26 40,25.3 v1(40,22)
  Bottom Layer w0.2: HDR2.62@38.9,16.5 38.9,19.5 38.9,20.9 v1(40,22)
LED2: HDR2.64 U1.E4 | length 18.1
  Top Layer w0.2: U1.E4@37,33.5 v1(37.5,33)
  MidLayer3 w0.127: 38,30.5 38,32.5
  MidLayer3 w0.2: v1(37.5,33) 38,32.5 ; 38,30.5 38,29.6 38.7,28.9 38.7,25.5 39.4,24.8 39.4,20.7 39.6,20.5 39.7,20.4 v1(39.7,18)
  Bottom Layer w0.2: HDR2.64@39.7,16.5 v1(39.7,18)
LED3: HDR2.66 U1.F3 | length 19.9
  Top Layer w0.2: v1(37.5,34) U1.F3@38,34.5
  MidLayer2 w0.127: 38,30.5 38,33.5
  MidLayer2 w0.2: v1(37.5,34) 38,33.5 ; 38,30.5 38,30 37.4,29.4 37.4,26.7 39.3,24.8 39.3,21.3 40.5,20.1 v1(40.5,19.5)
  Bottom Layer w0.2: HDR2.66@40.5,16.5 v1(40.5,19.5)
LED4: HDR2.68 U1.F4 | length 20.5
  Top Layer w0.2: v1(36.5,34) U1.F4@37,34.5
  MidLayer2 w0.127: 37,30.5 37,33.5
  MidLayer2 w0.2: v1(36.5,34) 37,33.5 ; 37,30.5 37,25.9 38.1,24.8 38.1,21.7 39.7,20.1 39.7,19 40.7,18 v1(41.3,18)
  Bottom Layer w0.2: HDR2.68@41.3,16.5 v1(41.3,18)
LED5: HDR2.70 U1.D1 | length 17.8
  Top Layer w0.2: U1.D1@40,32.5 40.5,32.5 ; 40.4,32.5 40.634,32.5 42.7,30.434 42.7,20.1 v1(42.1,19.5)
  Bottom Layer w0.2: HDR2.70@42.1,16.5 v1(42.1,19.5)
LED6: HDR2.72 U1.E2 | length 19.5
  Top Layer w0.2: U1.E2@39,33.5 39.5,33 40.7,33 43.1,30.6 43.1,18.2 v1(42.9,18)
  Bottom Layer w0.2: HDR2.72@42.9,16.5 v1(42.9,18)
LED7: HDR2.74 U1.E1 | length 19
  Top Layer w0.2: U1.E1@40,33.5 40.8,33.5 43.5,30.8 43.5,19.7 v1(43.7,19.5)
  Bottom Layer w0.2: HDR2.74@43.7,16.5 v1(43.7,19.5)
MOUSECLOCK: HDR1.26 U1.U14 | length 28.9
  Top Layer w0.2: v1(26.5,46) U1.U14@27,45.5
  MidLayer2 w0.127: 27,46.5 27,50.5
  MidLayer2 w0.2: v1(24.5,70) 24.5,61.6 27.3,58.8 27.3,51.8 27,51.5 27,50.5 ; v1(26.5,46) 27,46.5
  Bottom Layer w0.2: HDR1.26@24.5,67.3 v1(24.5,70)
MOUSEDATA: HDR1.28 U1.W14 | length 24.9
  Top Layer w0.2: U1.W14@27,47.5 v1(27.5,48)
  MidLayer2 w0.127: 28,48.5 28,49.5
  MidLayer2 w0.2: v1(25.3,69) 25.3,61.7 27.9,59.1 27.9,50.7 28.2,50.4 28.2,49.7 28,49.5 ; v1(27.5,48) 28,48.5
  Bottom Layer w0.2: HDR1.28@25.3,67.3 v1(25.3,69)
N_VRIO_ERR: R26.2 U1.W5 | length 41.4
  Top Layer w0.2: v1(35.5,48) U1.W5@36,47.5
  MidLayer1 w0.127: 36,48.5 36,49.5
  MidLayer1 w0.2: v1(35.5,48) 36,48.5 ; 36,49.5 36,52.9 35.9,53 35.9,54.2 36.6,54.9 36.6,58 37.2,58.6 37.2,62.9 40.5,66.2 45,70.7 45,77.6 44.6,78 44.6,79.1 v1(45.2,79.7)
  Bottom Layer w0.2: v1(45.2,79.7) 47,81.5 R26.2@49.05,81.5
NC0: U1.W7
NetC32_2: C32.2 R10.2 U2.2 U2.15 | length 13.7
  Top Layer w0.3: C32.2@4.85,9.5 6.1,9.5 8.4,7.2 8.4,6.588 ; U2.2@6.4,6.588 13.462,6.588 R10.2@14.55,5.5
NetC64_2: C64.2 U6.6 | length 8.7
  Top Layer w0.38: U6.6@57.015,40.548 58.652,40.548 61.8,37.5 63.9,37.5 64.275,37.125 C64.2@64.3,37.1
NetC67_1: C67.1 U6.10 | length 3.7
  Top Layer w0.38: U6.10@62.984,39.913 64.167,39.913 64.354,40.1 C67.1@66.5,40.1 ; C67.1@66.413,39.913 C67.1@66.5,40
NetC80_2: C80.2 L3.1 U1.AA15 | length 7
  Top Layer w0.2: v1(25.5,50) U1.AA15@26,49.5
  Bottom Layer w0.3: C80.2@24.5,50.65 23.5,51.65 23.5,53.8 24.425,54.725 24.5,54.8 L3.1@24.5,54.65 ; C80.2@24.7,50.8 v1(25.5,50)
NetC81_2: C81.2 L2.1 U1.AA16 | length 7.9
  Top Layer w0.2: v1(24.5,49) U1.AA16@25,49.5
  Bottom Layer w0.3: C81.2@22.5,50.65 21.6,51.55 21.6,53.7 L2.1@22.5,54.6 ; C81.2@22.7,50.8 v1(24.5,49)
NetC82_2: C82.2 L5.1 U1.AA14 | length 7.1
  Top Layer w0.2: v1(26.5,49) U1.AA14@27,49.5
  Bottom Layer w0.3: v1(26.5,49) C82.2@26.5,50.6 ; C82.2@26.5,50.65 25.5,51.65 25.5,53.6 26.5,54.6 L5.1@26.5,54.65
NetC83_2: C83.2 L4.1 U1.AA13 | length 6.8
  Top Layer w0.2: v1(27.5,50) U1.AA13@28,49.5
  Bottom Layer w0.3: v1(27.5,50) 27.5,50.7 ; C83.2@28.5,50.65 27.5,50.7 ; L4.1@28.5,54.65 28.45,54.65 27.5,53.7 27.5,50.7
NetC84_2: C84.2 L8.1 U1.AA7 | length 8.2
  Top Layer w0.2: U1.AA7@34,49.5 v1(34.5,49)
  Bottom Layer w0.3: v1(34.5,49) 35.5,50 35.5,50.6 ; C84.2@36.5,50.65 35.5,50.6 ; L8.1@36.5,54.65 36.5,54.5 35.5,53.5 35.5,50.6
NetC85_2: C85.2 L9.1 U1.AA8 | length 7.8
  Top Layer w0.2: U1.AA8@33,49.5 v1(33.5,50)
  Bottom Layer w0.3: v1(33.5,50) 33.5,50.7 ; L9.1@34.5,54.65 34.5,54.5 33.5,53.5 33.5,50.7 ; 33.5,50.7 33.55,50.65 C85.2@34.5,50.65 33.5,50.7
NetC86_2: C86.2 L6.1 U1.AA10 | length 7.4
  Top Layer w0.2: v1(30.5,49) U1.AA10@31,49.5
  Bottom Layer w0.3: v1(30.5,49) C86.2@30.5,50.65 29.4,51.75 29.4,53.7 30.4,54.7 L6.1@30.5,54.7
NetC87_2: C87.2 L7.1 U1.AA9 | length 7.8
  Top Layer w0.2: v1(31.5,50) U1.AA9@32,49.5
  Bottom Layer w0.3: v1(31.5,50) 31.5,50.7 ; C87.2@32.4,50.7 31.6,50.7 31.597,50.703 ; C87.2@32.5,50.65 32.425,50.725 31.597,50.703 ; L7.1@32.5,54.65 32.45,54.65 31.5,53.7 31.5,50.8 ; 31.5,50.7 31.5,50.8 ; 31.5,50.7 31.597,50.703 ; 31.5,50.8 31.597,50.703
NetC94_1: C94.1 U8.1 | length 2.6
  Bottom Layer w0.5: U8.1@58.1,78.905 C94.1@58.1,81.5
NetHDR1_56: HDR1.56 R1.2 | length 10.1
  Bottom Layer w0.2: R1.2@32.5,75 32.6,75 33.8,73.8 33.8,71.1 33.97,70.93 34.1,70.8 35.3,70.8 36.5,69.6 HDR1.56@36.5,67.3
NetHDR1_58: HDR1.58 R2.2 | length 5.7
  Bottom Layer w0.2: R2.2@35,72.05 35,71.8 37.3,69.5 HDR1.58@37.3,67.3
NetHDR1_60: HDR1.60 R3.2 | length 9.8
  Bottom Layer w0.2: R3.2@35.5,76.05 35.5,75.6 36.8,74.3 36.8,70.9 38.1,69.6 HDR1.60@38.1,67.3
NetHDR1_74: HDR1.74 R4.2 | length 4.3
  Bottom Layer w0.2: R4.2@43,71.05 R4.2@43.5,71.05 43.5,69.1 43.7,68.9 HDR1.74@43.7,67.3
NetHDR1_76: HDR1.76 R5.2 | length 8.1
  Bottom Layer w0.2: HDR1.76@44.5,67.3 44.5,69.4 44.8,69.7 44.8,73.5 45.5,74.3 R5.2@45.5,75.05
NetHDR1_86: HDR1.86 R6.2 | length 3.7
  Bottom Layer w0.2: HDR1.86@48.5,67.3 R6.2@48.5,71.05
NetL1_1: L1.1 U6.1 U6.3 U6.14 U6.16 | length 36.8
  Top Layer w0.38: U6.3@57.015,42.453 58.053,42.453 ; U6.1@57.015,43.723 U6.1@57.723,43.723 ; 58.3,43.4 57.977,43.723 ; 58.3,44.3 U6.1@57.723,43.723 ; 58.5,42.9 58.053,42.453 ; 61.4,43 61.947,42.453 ; 61.5,43.2 62.022,43.723 ; 61.5,44.4 U6.16@62.177,43.723 ; U6.14@62.984,42.453 61.947,42.453 ; U6.16@62.984,43.723 U6.16@62.177,43.723 ; U6.1@57.723,43.723 57.977,43.723 ; 57.977,43.723 59,43.723 60,43.723 61,43.723 62.022,43.723 ; 58.053,42.453 59.5,42.453 60.5,42.453 61.947,42.453 ; 62.022,43.723 U6.16@62.177,43.723
  Bottom Layer w1.5: v4(60,43.5) 60,44.548 60,48 62,50 L1.1@65,50 ; v4(60.5,42.5) 60.5,43.5 v4(60.5,44.548) 60.5,47.5 62,49 L1.1@64,49 ; 62,51 L1.1@63,51
  other v4: 59.5,42.5 59,43.5 61,43.5 59.5,44.548
NetLED1_1: LED1.1 R19.1 | length 2.1
  Top Layer w0.4: R19.1@46.5,5.5 LED1.1@48.55,5.5 LED1.1@48.6,5.5
NetLED2_1: LED2.1 R20.1 | length 4
  Top Layer w0.3: LED2.1@18.55,5.5 18.5,5.5 18.512,5.479 18.513,5.476 19.4,4.1 19.9,4.1 20.4,3.6 R20.1@20.4,2.5
NetLED2_2: LED2.2 U5.4 | length 3.4
  Top Layer w0.3: LED2.2@20.45,5.5 22,5.5 22.941,6.441 U5.4@23.42,6.441
NetR22_2: R22.2 U6.7 | length 2.8
  Top Layer w0.38: U6.7@57.015,39.913 57.987,39.913 v1(58.4,39.8)
  Bottom Layer w0.4: v1(58.4,39.8) 59,39.2 R22.2@59,38.6
NetR23_2: R23.2 R24.2 R25.1 U7.1 | length 10.2
  Bottom Layer w0.4: U7.1@18.5,79.04 21.14,79.04 22.6,80.5 R25.1@23.05,80.5 R23.2@23.05,85.5
NetR26_1: R26.1 R27.1 U8.7 | length 7.5
  Bottom Layer w0.5: R26.1@50.95,81.5 R26.1@51.1,81.5 ; U8.7@52.9,77.635 51.565,77.635 51.1,78.1 R26.1@51.1,81.5 ; R27.1@53.05,81.5 R26.1@51.1,81.5
NEXUS_TCK: HDR1.82 U1.W11 | length 40.4
  Top Layer w0.2: U1.W11@30,47.5 v1(30.5,47)
  MidLayer2 w0.127: 31,47.5 31.9,47.5 32,47.6 32,49.5
  MidLayer2 w0.2: v1(30.5,47) 31,47.5 ; 32,49.5 33.1,50.6 34.9,50.6 35.7,49.8 41.3,49.8 47.9,56.4 47.9,58.2 48.3,58.6 48.3,69.1 v1(47.6,69.8)
  Bottom Layer w0.2: HDR1.82@46.9,67.3 46.9,69.1 v1(47.6,69.8)
NEXUS_TDI: HDR1.84 U1.Y11 | length 37.3
  Top Layer w0.2: U1.Y11@30,48.5 v1(30.5,48)
  MidLayer2 w0.127: 31,48.5 31,49.5
  MidLayer2 w0.2: v1(30.5,48) 31,48.5 ; 31,49.5 30.8,49.7 30.8,50.3 31.5,51 35.1,51 35.9,50.2 41.134,50.2 46,55.066 46,58 47.1,59.1 47.1,64.1 47.7,64.7 v1(47.7,68.9)
  Bottom Layer w0.2: HDR1.84@47.7,67.3 v1(47.7,68.9)
NEXUS_TDO: R5.1 U1.AB2 | length 32.9
  Top Layer w0.2: U1.AB2@39,50.5 38.9,50.6 38.9,51.3 39.2,51.6 40.5,51.6 42.7,53.8 42.7,56.4 v1(43.3,57)
  MidLayer1 w0.2: v1(43.3,57) 43.1,57.2 43.1,58.1 43.6,58.6 43.6,68.4 45.5,70.3 v1(45.5,78.3)
  Bottom Layer w0.4: R5.1@45.5,76.95 v1(45.5,78.3)
NEXUS_TMS: HDR1.80 U1.V12 | length 36.2
  Top Layer w0.2: U1.V12@29,46.5 v1(29.5,47)
  MidLayer2 w0.127: 30,47.5 30,49.5
  MidLayer2 w0.2: v1(29.5,47) 30,47.5 ; 30,49.5 30,50.1 31.5,51.6 40.2,51.6 40.9,52.3 40.9,53.3 44.5,56.9 44.5,58 45.3,58.8 45.3,59.6 46.1,60.4 v1(46.1,68.9)
  Bottom Layer w0.2: HDR1.80@46.1,67.3 v1(46.1,68.9)
RAM0_DATA0: HDR2.42 U1.D10 | length 18.3
  Top Layer w0.2: v1(30.5,32) U1.D10@31,32.5
  MidLayer2 w0.127: 30,30.5 30,31.5
  MidLayer2 w0.2: 30,30.5 30,29.8 29.5,29.3 29.5,28 30.4,27.1 30.4,25.1 31.5,24 31.5,21.6 31.7,21.4 31.7,20.3 31.9,20.1 31.9,18.5 31.4,18 v1(30.9,18) ; 30,31.5 v1(30.5,32)
  Bottom Layer w0.2: HDR2.42@30.9,16.5 v1(30.9,18)
RAM0_DATA1: HDR2.40 U1.B11 | length 14.6
  Top Layer w0.2: U1.B11@30,30.5 29.5,30 29.5,28.1 29.7,27.9 29.7,19.9 v1(30.3,19.3)
  Bottom Layer w0.2: HDR2.40@30.1,16.5 30.1,18.2 30.3,18.4 v1(30.3,19.3)
RAM0_DATA2: HDR2.38 U1.B12 | length 15
  Top Layer w0.2: U1.B12@29,30.5 28.5,30 28.5,28.1 28.3,27.9 28.3,26.3 29.3,25.3 29.3,19.5 29.7,19.1 29.7,18.4 v1(29.3,18)
  Bottom Layer w0.2: HDR2.38@29.3,16.5 v1(29.3,18)
RAM0_DATA3: HDR2.36 U1.E13 | length 17.6
  Top Layer w0.2: v1(27.5,33) U1.E13@28,33.5
  MidLayer3 w0.127: 28,30.5 28,32.5
  MidLayer3 w0.2: v1(27.5,33) 28,32.5 ; 28,30.5 28,21 28.5,20.5 v1(28.5,19.5)
  Bottom Layer w0.2: HDR2.36@28.5,16.5 v1(28.5,19.5)
RAM0_DATA4: HDR2.34 U1.D13 | length 16.8
  Top Layer w0.2: v1(27.5,32) U1.D13@28,32.5
  MidLayer2 w0.127: 27,30.5 27,31.5
  MidLayer2 w0.2: 27,30.5 27.5,30 27.5,24.8 27.7,24.6 27.7,21 27.9,20.8 27.9,18.3 27.7,18.1 v1(27.7,18) ; 27,31.5 v1(27.5,32)
  Bottom Layer w0.2: HDR2.34@27.7,16.6 v1(27.7,18)
RAM0_DATA5: HDR2.32 U1.F14 | length 18.5
  Top Layer w0.2: U1.F14@27,34.5 v1(27.5,34)
  MidLayer4 w0.127: 27,30.5 27,33.5
  MidLayer4 w0.2: v1(26.9,19.5) 26.9,20.3 27,20.4 27,30.5 ; 27,33.5 v1(27.5,34)
  Bottom Layer w0.2: HDR2.32@26.9,16.5 v1(26.9,19.5)
RAM0_DATA6: HDR2.30 U1.C13 | length 16
  Top Layer w0.2: v1(27.5,31) U1.C13@28,31.5
  MidLayer1 w0.2: v1(26.1,18) 26.4,18 27.5,19.1 v1(27.5,31)
  Bottom Layer w0.2: HDR2.30@26.1,16.5 v1(26.1,18)
RAM0_DATA7: HDR2.28 U1.C15 | length 15.4
  Top Layer w0.2: v1(25.5,31) U1.C15@26,31.5
  MidLayer1 w0.2: v1(25.3,19.5) 25.3,19.9 25.2,20 25.2,22.9 25.5,23.2 v1(25.5,31)
  Bottom Layer w0.2: HDR2.28@25.3,16.5 v1(25.3,19.5)
RAM0_OE: HDR1.41 U1.U10 | length 16.1
  Top Layer w0.2: U1.U10@31,45.5 v1(31.5,46)
  MidLayer1 w0.127: 32,46.5 32,50.5
  MidLayer1 w0.2: v1(30.6,58.9) 31.4,58.1 31.4,52.9 32,52.3 32,50.5 ; v1(31.5,46) 32,46.5
  Bottom Layer w0.2: v1(30.6,58.9) 30.9,59.2 HDR1.41@30.9,60.5
RAM0_WE: HDR1.79 U1.W1 | length 16.9
  Top Layer w0.2: U1.W1@40,47.5 42.4,47.5 43.3,48.4 v1(43.3,50.4)
  MidLayer1 w0.2: v1(43.3,50.4) 43.3,52.9 45.9,55.5 45.9,57.5 46.1,57.7 v1(46.1,58.9)
  Bottom Layer w0.2: v1(46.1,58.9) HDR1.79@46.1,60.5
RAM1_DATA0: HDR1.45 U1.V10 | length 17.3
  Top Layer w0.2: U1.V10@31,46.5 v1(31.5,47)
  MidLayer3 w0.127: 31,47.5 31,50.5
  MidLayer3 w0.2: v1(29.4,57.2) 29.4,57 31,55.4 31,50.5 ; 31,47.5 v1(31.5,47)
  MidLayer4 w0.2: v1(29.4,57.2) 29.8,57.5 30.5,58.2 32,58.2 32.6,58.8 v1(32.6,58.9)
  Bottom Layer w0.2: HDR1.45@32.5,60.5 32.5,59.1 v1(32.6,58.9)
RAM1_DATA1: HDR1.49 U1.Y8 | length 15.2
  Top Layer w0.2: U1.Y8@33,48.5 v1(33.5,48)
  MidLayer1 w0.127: 34,48.5 34.9,48.5 35,48.6 35,49.5
  MidLayer1 w0.2: v1@33.5,48.1 v1(33.5,48) 34,48.5 ; v1(34.5,57.4) 34.5,56.1 35.5,55.1 35.5,50 35,49.5
  Bottom Layer w0.2: HDR1.49@34.1,60.5 34.1,58 v1(34.5,57.4)
RAM1_DATA2: HDR1.53 U1.N6 | length 22.6
  Top Layer w0.2: U1.N6@35,41.5 v1(35.5,41)
  MidLayer3 w0.127: 35,41.5 35,42.5 ; 37,46.4 37,47.8 37.997,48.797 37.997,49.497
  MidLayer3 w0.2: 35,41.5 v1(35.5,41) ; 35,42.5 35.5,43 35.5,44.9 37,46.4 ; v1(35.7,57.6) 35.7,57.1 37.5,55.3 37.5,50 38,49.5
  Bottom Layer w0.2: v1(35.7,57.6) HDR1.53@35.7,60.5
RAM1_DATA3: HDR1.57 U1.V4 | length 15.1
  Top Layer w0.2: U1.V4@37,46.5 v1(37.5,47)
  MidLayer1 w0.2: v1(37.3,57.7) 37.3,55.5 38.3,54.5 38.3,48.8 37.5,48 v1(37.5,47)
  Bottom Layer w0.2: v1@37.3,57.6 v1(37.3,57.7) HDR1.57@37.3,60.5
RAM1_DATA4: HDR1.55 U1.M6 | length 26.1
  Top Layer w0.2: U1.M6@35,40.5 v1(35.5,40)
  MidLayer3 w0.127: 36,40.5 36,42.3 36.2,42.5 39,42.5
  MidLayer3 w0.2: v1(35.5,40) 36,40.5 ; v1(36.5,58.9) 36.5,58.3 36.3,58.1 36.3,57.2 37.9,55.6 37.9,50.166 38.366,49.7 38.4,49.7 38.4,48.686 37.9,48.186 37.9,47.7 39.2,46.4 39.2,42.7 39,42.5
  Bottom Layer w0.2: v1(36.5,58.9) HDR1.55@36.5,60.5
RAM1_DATA5: HDR1.51 U1.V8 | length 19.2
  Top Layer w0.2: U1.V8@33,46.5 v1(33.5,46)
  MidLayer3 w0.127: 34,46.5 34.9,46.5 35,46.6 35,47.4 35.1,47.5 35.9,47.5 36,47.6 36,48.4 36.1,48.5 36.9,48.5 37,48.6 37,49.5
  MidLayer3 w0.2: v1(33.5,46) 34,46.5 ; v1(35.1,58.3) 35.1,56.9 34.9,56.7 34.9,56 35.661,55.239 35.661,52.339 37,51 37,49.5
  Bottom Layer w0.2: HDR1.51@34.9,60.5 34.9,58.5 v1(35.1,58.3)
RAM1_DATA6: HDR1.47 U1.V9 | length 15
  Top Layer w0.2: U1.V9@32,46.5 v1(32.5,47)
  MidLayer1 w0.127: 33,47.5 33,50.5
  MidLayer1 w0.2: v1(32.5,47) 33,47.5 ; v1(32.6,57.5) 32.6,56.6 33.1,56.1 33.1,52.7 33,52.6 33,50.5
  Bottom Layer w0.2: v1(32.6,57.5) 33.3,58.2 HDR1.47@33.3,60.5
RAM1_DATA7: HDR1.43 U1.W10 | length 14
  Top Layer w0.2: U1.W10@31,47.5 v1(31.5,48)
  MidLayer1 w0.127: 31,48.5 31,50.5
  MidLayer1 w0.2: v1(30.6,57.4) 30.6,54.5 31,54.1 31,50.5 ; 31,48.5 v1(31.5,48)
  Bottom Layer w0.2: v1(30.6,57.4) 31.7,58.7 HDR1.43@31.7,60.5
RAM1_OE: HDR1.39 U1.AA11 | length 12
  Top Layer w0.2: v1(29.7,58.2) 30,57.9 30,56.9 30.239,56.661 30.239,54.261 30.7,53.8 30.8,53.7 30.8,53 30.5,52.7 30.5,50 U1.AA11@30,49.5
  Bottom Layer w0.2: v1(29.7,58.2) 29.952,58.452 29.952,59.352 30.1,59.5 HDR1.39@30.1,60.5
RAM1_WE: HDR1.61 U1.M4 | length 24
  Top Layer w0.2: U1.M4@37,40.5 v1(37.5,40)
  MidLayer3 w0.127: 38,40.5 39,40.5
  MidLayer3 w0.2: v1(37.5,40) 38,40.5 ; v1(38.9,57.7) 39.386,57.214 39.686,57.214 40.7,56.2 40.7,42.2 39,40.5
  Bottom Layer w0.2: v1(38.9,57.7) HDR1.61@38.9,60.5
RAM_ADDR0: HDR1.21 U1.Y16 | length 14.6
  Top Layer w0.2: U1.Y16@25,48.5 v1(25.5,48)
  MidLayer1 w0.127: 25,48.5 25,49.5
  MidLayer1 w0.2: v1(23.7,58) 23.7,56.9 24.8,55.8 24.8,49.7 25,49.5 ; 25,48.5 v1(25.5,48)
  Bottom Layer w0.2: HDR1.21@22.9,60.5 22.9,58.3 23.2,58 v1(23.7,58)
RAM_ADDR1: HDR1.25 U1.Y15 | length 13.3
  Top Layer w0.2: v1(25.5,49) U1.Y15@26,48.5
  MidLayer2 w0.2: v1(24.3,57.4) 25.7,56 25.7,51 26.086,50.614 26.086,49.586 v1(25.5,49)
  Bottom Layer w0.2: v1(24.3,57.4) 24.5,57.5 HDR1.25@24.5,60.5
RAM_ADDR2: HDR1.29 U1.V13 | length 16.2
  Top Layer w0.2: U1.V13@28,46.5 v1(28.5,47)
  MidLayer3 w0.127: 28,47.5 28,49.5
  MidLayer3 w0.2: v1(25.9,58) 27,58 27.6,57.4 27.6,53.4 28.2,52.8 28.2,49.7 28,49.5 ; 28,47.5 v1(28.5,47)
  Bottom Layer w0.2: v1(25.9,58) 25.9,59.1 26.1,59.3 HDR1.29@26.1,60.5
RAM_ADDR3: HDR1.33 U1.Y13 | length 13.6
  Top Layer w0.2: v1(27.5,49) U1.Y13@28,48.5
  MidLayer1 w0.2: v1(26.5,57.4) 27.2,56.7 27.2,51.4 28.1,50.5 28.1,49.6 v1(27.5,49)
  Bottom Layer w0.2: v1(26.5,57.4) 27.7,58.6 HDR1.33@27.7,60.5
RAM_ADDR4: HDR1.65 U1.M3 | length 22.1
  Top Layer w0.2: U1.M3@38,40.5 v1(38.5,40)
  MidLayer1 w0.2: v1(38.5,40) 40.5,42 v1(40.5,57.3)
  Bottom Layer w0.2: v1(40.5,57.3) HDR1.65@40.5,60.5 HDR1.65@40.5,60.6
RAM_ADDR5: HDR1.69 U1.W2 | length 16.4
  Top Layer w0.2: U1.W2@39,47.5 39.5,48 41.1,48 41.2,48.1 v1(42.1,48.1)
  MidLayer1 w0.2: v1(42.1,48.1) 41.3,48.9 41.3,56.9 v1(42.1,57.7)
  Bottom Layer w0.2: v1(42.1,57.7) HDR1.69@42.1,60.5
RAM_ADDR6: HDR1.73 U1.AA1 | length 12.8
  Top Layer w0.2: U1.AA1@40,49.5 43.2,52.7 43.2,55.8 44,56.6 44,57.4 v1(43.7,57.7)
  Bottom Layer w0.2: v1(43.7,57.7) HDR1.73@43.7,60.5
RAM_ADDR7: HDR1.77 U1.V2 | length 21.9
  Top Layer w0.2: U1.V2@39,46.5 39.5,46 43.7,46 43.9,46.2 v1(44.4,46.2)
  MidLayer1 w0.2: v1(44.4,46.2) 43.7,46.9 43.7,47 43.2,47.5 43.2,49.6 42.5,50.3 42.5,54.9 v1(45.3,57.7)
  Bottom Layer w0.2: v1(45.3,57.7) HDR1.77@45.3,60.5
RAM_ADDR8: HDR1.75 U1.Y2 | length 15.6
  Top Layer w0.2: U1.Y2@39,48.5 39.5,49 40.3,49 45.5,54.2 45.5,56 44.5,57 v1(44.5,58.9)
  Bottom Layer w0.2: v1(44.5,58.9) HDR1.75@44.5,60.5
RAM_ADDR9: HDR1.71 U1.V3 | length 19.1
  Top Layer w0.2: U1.V3@38,46.5 38.5,47 v1(42.8,47)
  MidLayer1 w0.2: v1(42.8,47) 42.8,49.3 42.1,50 42.1,55.9 42.7,56.5 42.7,58.7 v1(42.9,58.9)
  Bottom Layer w0.2: v1(42.9,58.9) HDR1.71@42.9,60.5
RAM_ADDR10: HDR1.67 U1.L3 | length 25.4
  Top Layer w0.2: U1.L3@38,39.5 v1(38.5,39)
  MidLayer3 w0.2: v1(38.5,39) 39.2,38.3 39.9,38.3 40.3,38.7 40.3,39.4 40.8,39.9 40.9,39.9 41.5,40.5 41.5,58.2 41.3,58.4 v1(41.3,58.9)
  Bottom Layer w0.2: v1(41.3,58.9) HDR1.67@41.3,60.5
RAM_ADDR11: HDR1.63 U1.L4 | length 25.2
  Top Layer w0.2: U1.L4@37,39.5 v1(37.5,39)
  MidLayer3 w0.127: 38,39.5 39,39.5
  MidLayer3 w0.2: v1(37.5,39) 38,39.5 ; 39,39.5 39.4,39.9 39.4,40.2 41.1,41.9 41.1,58 40.2,58.9 v1(39.7,58.9)
  Bottom Layer w0.2: v1(39.7,58.9) HDR1.63@39.7,60.5
RAM_ADDR12: HDR1.59 U1.M5 | length 25.1
  Top Layer w0.2: U1.M5@36,40.5 v1(36.5,40)
  MidLayer3 w0.127: 37,40.5 37,41.4 37.1,41.5 39,41.5
  MidLayer3 w0.2: v1(36.5,40) 37,40.5 ; v1(38.1,58.9) 38.1,57.7 39,56.8 39.534,56.8 40.3,56.034 40.3,42.8 39,41.5
  Bottom Layer w0.2: v1(38.1,58.9) HDR1.59@38.1,60.5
